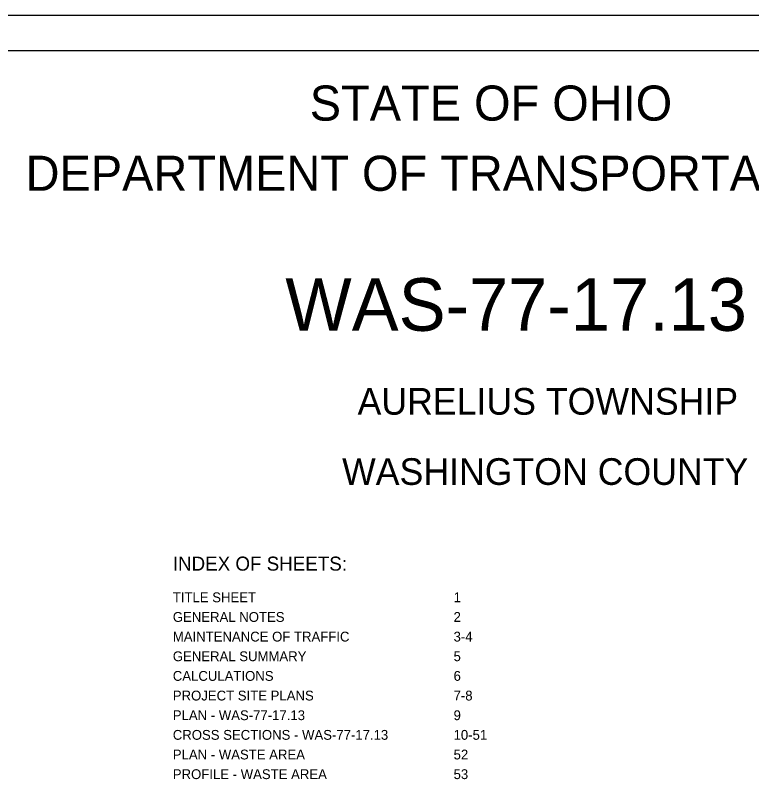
# Model space of a CAD drawing. Extents: x 0 to 34, y 0 to 22.
# Drawn here: x 9.6 to 20.09, y 11.07 to 22 of the extents above; entities that cross this region are included whole.
import ezdxf

# ---------------------------------------------------------------- set-up
doc = ezdxf.new("R2010")
doc.units = 0
for name, color, linetype in [('SH_Border', 7, 'Continuous'), ('SH_Cut_Line', 7, 'Continuous'), ('SH_Text', 7, 'Continuous')]:
    doc.layers.add(name, color=color, linetype=linetype)

msp = doc.modelspace()

# ---------------------------------------------------------------- linework, layer by layer
at = {"layer": 'SH_Border'}
msp.add_lwpolyline([(1.5, 21.5), (33.5, 21.5), (33.5, 0.5), (1.5, 0.5)], close=True, dxfattribs=at)
at = {"layer": 'SH_Cut_Line'}
msp.add_lwpolyline([(0, 0), (34, 0), (34, 22), (0, 22)], close=True, dxfattribs=at)

# ---------------------------------------------------------------- texts
at = {"layer": 'SH_Text'}
for s, height, p in [('STATE OF OHIO', 0.5, (13.795, 20.5)), ('DEPARTMENT OF TRANSPORTATION', 0.5, (9.747, 19.5)), ('WAS-77-17.13', 0.75, (13.446, 17.505)), ('  AURELIUS TOWNSHIP ', 0.38, (14.194, 16.31)), ('  WASHINGTON COUNTY ', 0.38, (13.973, 15.31)), ('INDEX OF SHEETS:', 0.2, (11.844, 14.088)), ('TITLE SHEET                        ', 0.14, (11.844, 13.638)), ('1      ', 0.14, (15.844, 13.638)), ('GENERAL NOTES                      ', 0.14, (11.844, 13.358)), ('2      ', 0.14, (15.844, 13.358)), ('MAINTENANCE OF TRAFFIC             ', 0.14, (11.844, 13.078)), ('3-4    ', 0.14, (15.844, 13.078)), ('GENERAL SUMMARY                    ', 0.14, (11.844, 12.798)), ('5      ', 0.14, (15.844, 12.798)), ('CALCULATIONS                       ', 0.14, (11.844, 12.518)), ('6      ', 0.14, (15.844, 12.518)), ('PROJECT SITE PLANS                 ', 0.14, (11.844, 12.238)), ('7-8    ', 0.14, (15.844, 12.238)), ('PLAN - WAS-77-17.13                ', 0.14, (11.844, 11.958)), ('9      ', 0.14, (15.844, 11.958)), ('CROSS SECTIONS - WAS-77-17.13      ', 0.14, (11.844, 11.678)), ('10-51  ', 0.14, (15.844, 11.678)), ('PLAN - WASTE AREA                  ', 0.14, (11.844, 11.398)), ('52     ', 0.14, (15.844, 11.398)), ('PROFILE - WASTE AREA               ', 0.14, (11.844, 11.118)), ('53     ', 0.14, (15.844, 11.118))]:
    msp.add_text(s, height=height, dxfattribs=at).set_placement(p)

doc.saveas('drawing.dxf')
